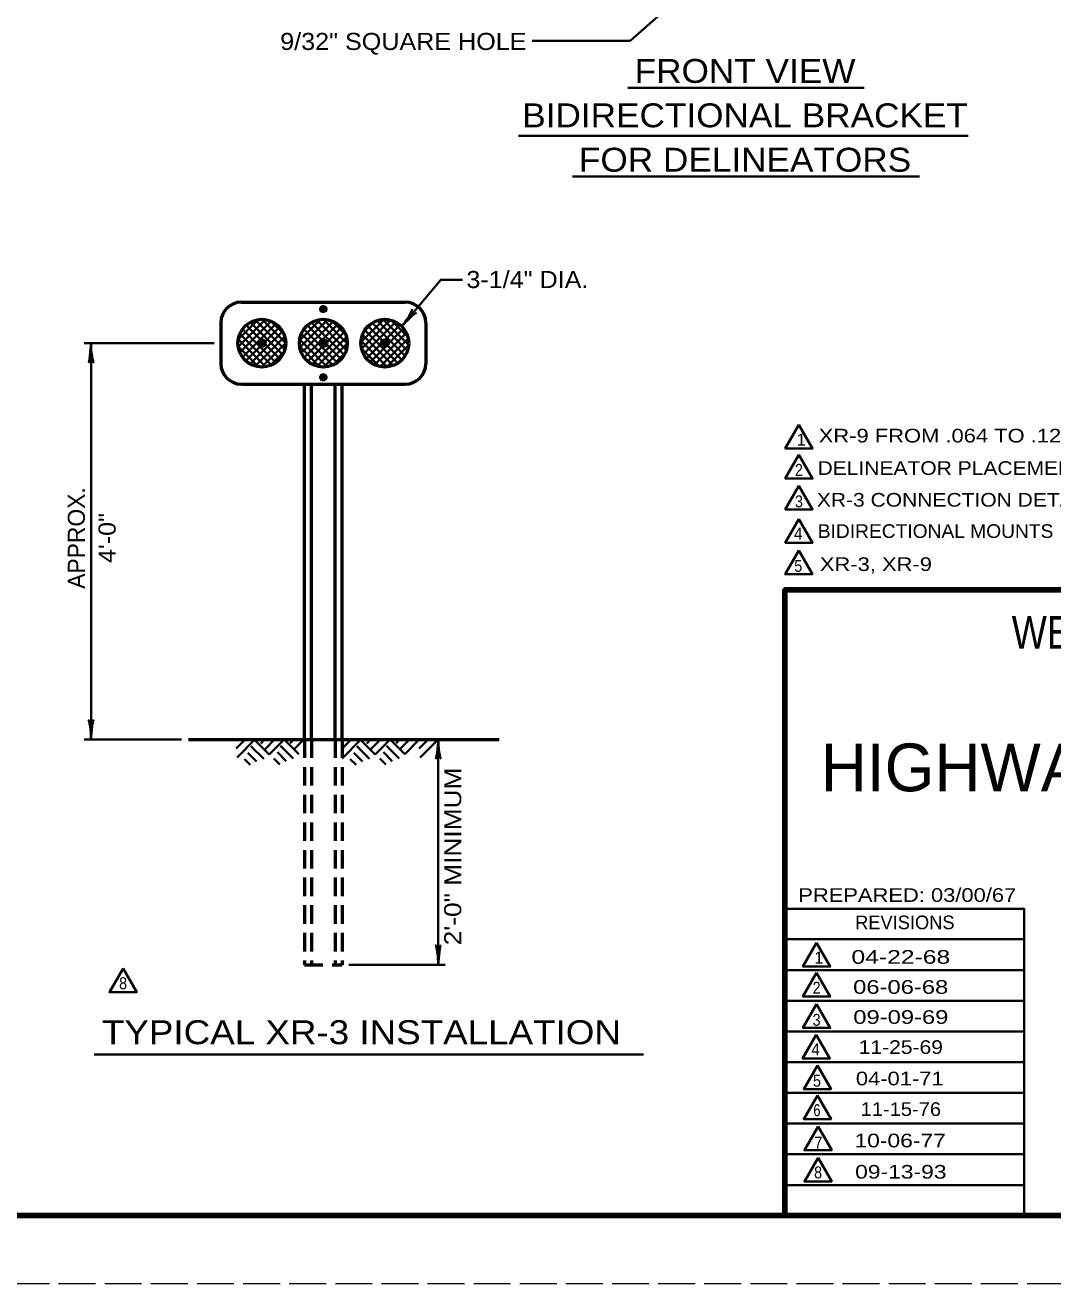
# Model space of a CAD drawing. Extents: x -54 to 626, y -41 to 399.
# Drawn here: x 331.9 to 482.3, y -41.3 to 142.9 of the extents above; entities that cross this region are included whole.
import ezdxf
from ezdxf.enums import TextEntityAlignment as Align

# ---------------------------------------------------------------- set-up
doc = ezdxf.new("R2010")
doc.units = 0
doc.header["$LTSCALE"] = 0.9
doc.linetypes.add('LONG_DASHED', pattern=[7.5, 6, -1.5])
doc.linetypes.add('MEDIUM_DASHED', pattern=[4.5, 3, -1.5])
doc.layers.add('1', color=7, linetype='Continuous', lineweight=35)
doc.layers.add('61', color=7, linetype='Continuous', lineweight=35)

msp = doc.modelspace()

# ---------------------------------------------------------------- hatches: boundary and pattern name
at = {"layer": '1'}
for points in [[(375.8723, 101.3772, 1), (375.1223, 101.3772, 1)], [(366.9973, 96.3772, 1), (365.9973, 96.3772, 1)], [(375.9973, 96.3772, 1), (374.9973, 96.3772, 1)], [(384.9973, 96.3772, 1), (383.9973, 96.3772, 1)], [(375.8723, 91.3772, 1), (375.1223, 91.3772, 1)]]:
    msp.add_hatch(color=256, dxfattribs=at).paths.add_polyline_path(points)

# ---------------------------------------------------------------- linework, layer by layer
at = {"layer": '1', "lineweight": 40}
for p, q in [((420.0461, 133.771), (454.6423, 133.771)), ((404.0612, 126.7473), (469.8797, 126.7473)), ((411.9789, 120.7698), (462.75, 120.7698)), ((341.9621, -7.7556), (422.3773, -7.7556))]:
    msp.add_line(p, q, dxfattribs=at)
at = {"layer": '1', "lineweight": 53}
for p, q in [((363.4973, 102.3772), (387.4973, 102.3772)), ((360.4973, 99.3772), (360.4973, 93.3772)), ((390.4973, 99.3772), (390.4973, 93.3772)), ((363.4973, 90.3772), (387.4973, 90.3772)), ((372.7473, 38.3772), (372.7473, 90.3772)), ((373.7473, 38.3772), (373.7473, 90.3772)), ((377.2473, 38.3772), (377.2473, 90.3772)), ((378.2473, 38.3772), (378.2473, 90.3772)), ((355.7473, 38.3772), (401.2473, 38.3772)), ((362.7473, 38.3772), (372.7473, 38.3772)), ((378.2473, 38.3772), (391.2473, 38.3772))]:
    msp.add_line(p, q, dxfattribs=at)
at = {"layer": '1'}
for p, q in [((363.0416, 96.9052), (365.9697, 99.8332)), ((363.042, 95.8449), (367.0292, 99.8322)), ((363.2739, 95.0162), (367.8578, 99.6002)), ((369.8656, 95.4361), (365.5557, 99.7459)), ((369.9965, 96.3657), (366.4857, 99.8766)), ((369.7433, 97.6797), (367.7995, 99.6234)), ((372.0235, 96.7808), (375.0932, 99.8506)), ((372.0598, 95.7564), (376.1179, 99.8146)), ((372.3092, 94.9452), (376.9291, 99.5651)), ((378.8588, 95.4161), (374.5358, 99.7392)), ((378.9949, 96.3407), (375.4607, 99.8749)), ((378.7571, 97.6392), (376.7591, 99.6372)), ((381.0072, 96.5281), (384.3465, 99.8673)), ((381.0992, 95.5594), (385.3152, 99.7755)), ((387.8011, 95.2447), (383.3649, 99.681)), ((387.9811, 96.1255), (384.2458, 99.8607)), ((387.8748, 97.2923), (385.4127, 99.7545)), ((367.8897, 93.1693), (363.2898, 97.7692)), ((363.6583, 94.3399), (368.5347, 99.2163)), ((368.5625, 93.5572), (363.6768, 98.4428)), ((364.1602, 93.7812), (369.0931, 98.7141)), ((369.1151, 94.0652), (364.1853, 98.9949)), ((364.7727, 93.3331), (369.541, 98.1013)), ((369.5568, 94.6841), (364.8046, 99.4364)), ((376.8717, 93.1605), (372.281, 97.7512)), ((377.5465, 93.5464), (372.6662, 98.4267)), ((372.7009, 94.2763), (377.5983, 99.1737)), ((372.9383, 98.7563), (373.1158, 98.9339)), ((378.1026, 94.051), (373.1712, 98.9824)), ((373.217, 93.7317), (378.1427, 98.6575)), ((378.5481, 94.6662), (373.7867, 99.4275)), ((373.8441, 93.2981), (378.5762, 98.0302)), ((381.3874, 94.787), (386.0875, 99.4871)), ((381.3887, 97.9702), (382.9039, 99.4855)), ((386.4095, 93.4544), (381.5746, 98.2893)), ((381.8078, 94.1467), (386.7276, 99.0664)), ((386.9958, 93.9287), (382.0492, 98.8753)), ((382.3432, 93.6214), (387.2532, 98.5315)), ((387.4599, 94.5252), (382.6451, 99.3401)), ((383.0027, 93.2202), (387.6542, 97.8718)), ((359.4973, 96.3772), (340.4973, 96.3772)), ((341.4973, 96.3772), (341.4973, 38.3772)), ((366.0276, 92.9101), (363.0292, 95.9084)), ((367.0687, 92.9297), (363.0501, 96.9483)), ((365.521, 93.0207), (369.854, 97.3537)), ((366.4421, 92.8811), (369.9936, 96.4326)), ((374.9943, 92.9167), (372.036, 95.875)), ((376.0464, 92.9252), (372.0457, 96.9259)), ((374.6008, 92.9942), (378.8799, 97.2733)), ((375.5473, 92.8801), (378.994, 96.3267)), ((384.8426, 92.9), (381.0197, 96.7228)), ((385.7043, 93.0989), (381.2188, 97.5845)), ((383.7983, 92.9552), (387.9192, 97.0761)), ((384.801, 92.8972), (387.9778, 96.074)), ((367.7289, 93.1072), (369.768, 95.1463)), ((376.9047, 93.1767), (378.6961, 94.9682)), ((383.7092, 92.9728), (381.0933, 95.5886)), ((386.4378, 93.4734), (387.401, 94.4366)), ((354.7473, 38.3772), (340.4973, 38.3772)), ((364.0673, 38.3372), (362.7473, 37.0172)), ((365.4872, 38.3372), (362.8673, 35.7172)), ((364.9072, 37.3772), (366.7672, 35.5372)), ((365.3872, 38.3372), (367.5872, 36.1372)), ((366.9072, 38.3372), (366.3472, 37.7572)), ((368.3472, 38.3372), (366.9672, 36.9572)), ((369.7672, 38.3372), (367.5872, 36.1372)), ((369.2473, 37.4372), (371.0872, 35.5972)), ((369.7672, 38.3372), (371.9072, 36.1972)), ((371.1873, 38.3372), (370.6672, 37.8172)), ((372.6273, 38.3372), (371.3073, 37.0172)), ((379.5673, 38.3372), (378.2473, 37.0172)), ((380.9872, 38.3372), (378.2473, 35.5972)), ((380.4072, 37.3772), (382.2672, 35.5372)), ((380.8872, 38.3372), (383.0872, 36.1372)), ((382.4072, 38.3372), (381.8472, 37.7572)), ((383.8472, 38.3372), (382.4672, 36.9572)), ((385.2672, 38.3372), (383.0872, 36.1372)), ((384.7473, 37.4372), (386.5872, 35.5972)), ((385.2672, 38.3372), (387.4072, 36.1972)), ((386.6873, 38.3372), (386.1672, 37.8172)), ((388.1273, 38.3372), (386.8073, 37.0172)), ((389.5472, 38.3372), (387.4072, 36.1972)), ((390.8673, 38.3372), (389.5472, 37.0172)), ((392.3272, 38.3772), (389.6672, 35.7172)), ((392.3237, 38.3772), (392.3237, 5.3772)), ((363.9472, 35.4972), (364.8073, 34.6572)), ((364.4472, 36.4172), (365.7272, 35.1372)), ((368.2672, 35.5572), (369.1273, 34.6972)), ((368.7872, 36.4772), (370.0673, 35.1972)), ((379.4472, 35.4972), (380.3073, 34.6572)), ((379.9472, 36.4172), (381.2272, 35.1372)), ((383.7672, 35.5572), (384.6273, 34.6972)), ((384.2872, 36.4772), (385.5673, 35.1972)), ((478.0577, 9.1039), (443.0777, 9.1039)), ((379.2473, 5.3772), (393.3237, 5.3772)), ((478.0577, 4.6039), (443.0777, 4.6039)), ((478.0577, 0.1039), (443.0777, 0.1039)), ((478.0577, -4.4161), (443.0777, -4.4161)), ((478.0577, -8.8961), (443.0777, -8.8961)), ((478.0577, -13.3761), (443.0777, -13.3761)), ((478.0577, -17.8761), (443.0777, -17.8761)), ((478.0577, -22.3761), (443.0777, -22.3761)), ((478.0577, -26.8961), (443.0777, -26.8961))]:
    msp.add_line(p, q, dxfattribs=at)
at = {"layer": '1', "linetype": 'MEDIUM_DASHED', "lineweight": 53}
for p, q in [((372.7473, 38.3772), (372.7473, 5.3772)), ((373.7473, 38.3772), (373.7473, 5.3772)), ((377.2473, 38.3772), (377.2473, 5.3772)), ((378.2473, 38.3772), (378.2473, 5.3772)), ((372.7473, 5.3772), (378.2473, 5.3772))]:
    msp.add_line(p, q, dxfattribs=at)
at = {"layer": '1'}
for points in [[(432.2431, 151.1188), (420.4005, 140.6441), (406.0473, 140.6441)], [(386.9721, 98.852), (392.6807, 105.6705), (395.8748, 105.6705)], [(478.0577, -31.3761), (478.0577, 13.5839), (443.0777, 13.5839)]]:
    msp.add_lwpolyline(points, dxfattribs=at)
for points in [[(445.1058, 84.4172), (443.1058, 80.9531), (447.1058, 80.9531)], [(445.1058, 80.0091), (443.1058, 76.545), (447.1058, 76.545)], [(445.1137, 75.5101), (443.1137, 72.046), (447.1137, 72.046)], [(445.1137, 70.6202), (443.1137, 67.1561), (447.1137, 67.1561)], [(445.0852, 66.0081), (443.0852, 62.544), (447.0852, 62.544)], [(447.6912, 8.5772), (445.6912, 5.1131), (449.6912, 5.1131)], [(346.1998, 4.8243), (344.1998, 1.3602), (348.1998, 1.3602)], [(447.6912, 4.1806), (445.6912, 0.7165), (449.6912, 0.7165)], [(447.6993, -0.3995), (445.6993, -3.8636), (449.6993, -3.8636)], [(447.6532, -4.8845), (445.6532, -8.3486), (449.6532, -8.3486)], [(447.8239, -9.367), (445.8239, -12.8311), (449.8239, -12.8311)], [(447.824, -13.7637), (445.824, -17.2278), (449.824, -17.2278)], [(447.905, -18.3087), (445.905, -21.7727), (449.905, -21.7727)], [(447.927, -22.8768), (445.927, -26.3409), (449.927, -26.3409)]]:
    msp.add_lwpolyline(points, close=True, dxfattribs=at)
at = {"layer": '1', "lineweight": 158}
msp.add_lwpolyline([(443.0577, -31.3361), (443.0577, 60.2439), (614.7178, 60.2439)], dxfattribs=at)
at = {"layer": '1', "lineweight": 53}
for centre, radius in [((375.4973, 101.3772), 0.375), ((366.4973, 96.3772), 3.5), ((375.4973, 96.3772), 3.5), ((384.4973, 96.3772), 3.5), ((366.4973, 96.3772), 0.5), ((375.4973, 96.3772), 0.5), ((384.4973, 96.3772), 0.5), ((375.4973, 91.3772), 0.375)]:
    msp.add_circle(centre, radius, dxfattribs=at)
for centre, start, end in [((363.4973, 99.3772), 90, 180), ((387.4973, 99.3772), 0, 90), ((363.4973, 93.3772), 180, 270), ((387.4973, 93.3772), 270, 0)]:
    msp.add_arc(centre, 3, start, end, dxfattribs=at)
at = {"layer": '1', "lineweight": 40}
for centre, major_axis, ratio, start_param, end_param in [((387.4607, 99.866), (-1.0266, -1.4694), 0.122415, 0.89635335, 3.14159265), ((387.8536, 99.5753), (1.2622, 1.234), 0.07063, 6.28230741, 8.55970261), ((341.2856, 95.2567), (0.1757, 1.7565), 0.07063, 3.14071475, 5.41810995), ((341.2856, 95.2567), (0.1757, 1.7565), 0.07063, 3.14071475, 5.41810995), ((341.7735, 95.286), (-0.1562, 1.7857), 0.122415, 0.89635335, 3.14159265), ((341.7735, 95.286), (-0.1562, 1.7857), 0.122415, 0.89635335, 3.14159265), ((341.221, 39.4684), (0.1562, -1.7857), 0.122415, 0.89635335, 3.14159265), ((341.7089, 39.4977), (-0.1757, -1.7565), 0.07063, 3.14071475, 5.41810995), ((392.1121, 37.2567), (0.1757, 1.7565), 0.07063, 3.14071475, 5.41810995), ((392.1121, 37.2567), (0.1757, 1.7565), 0.07063, 3.14071475, 5.41810995), ((392.6, 37.286), (-0.1562, 1.7857), 0.122415, 0.89635335, 3.14159265), ((392.6, 37.286), (-0.1562, 1.7857), 0.122415, 0.89635335, 3.14159265), ((392.0475, 6.4684), (0.1562, -1.7857), 0.122415, 0.89635335, 3.14159265), ((392.5354, 6.4977), (-0.1757, -1.7565), 0.07063, 3.14071475, 5.41810995)]:
    msp.add_ellipse(centre, major_axis=major_axis, ratio=ratio, start_param=start_param, end_param=end_param, dxfattribs=at)
at = {"layer": '61', "lineweight": 158}
msp.add_line((614.7178, -31.3361), (-24.3422, -31.3161), dxfattribs=at)
at = {"layer": '61', "linetype": 'LONG_DASHED', "lineweight": 13}
msp.add_line((625.6577, -41.3161), (-54.4022, -41.3361), dxfattribs=at)

# ---------------------------------------------------------------- texts
at = {"layer": '1'}
for s, height, width, p in [('9/32" SQUARE HOLE', 2.5, 1.1, (369.1856, 139.3047)), ('3-1/4" DIA.', 2.5, 1.1, (396.4385, 104.4488)), ('XR-9 FROM .064 TO .125, SPACING FORMULA ADDED, MEDIAN DETAIL.', 2, 1.2, (448.0093, 81.8416)), ('2', 1.75, 0.9, (444.525, 76.9551)), ('DELINEATOR PLACEMENT ON RAMP', 2, 1.15, (447.8386, 77.0917)), ('3', 1.75, 0.9, (444.525, 72.3419)), ('XR-3 CONNECTION DETAIL.', 2, 1.15, (447.7361, 72.4444)), ('4', 1.75, 0.95, (444.3883, 67.6262)), ('BIDIRECTIONAL MOUNTS', 2, 1.05, (447.8727, 67.8655)), ('5', 1.75, 0.9, (444.4251, 62.897)), ('XR-3, XR-9', 2, 1.2, (448.1757, 63.0242)), ('PREPARED: 03/00/67', 1.998, 1.2, (445.0177, 14.5839)), ('8', 1.75, 0.9, (345.6033, 1.7971)), ('2', 1.75, 0.9, (447.1104, 1.1266)), ('3', 1.75, 0.9, (447.1105, -3.5677)), ('TYPICAL XR-3 INSTALLATION', 3.5, 1.15, (343.0894, -6.252)), ('4', 1.75, 0.95, (446.9278, -7.8784)), ('5', 1.75, 0.9, (447.1638, -12.4781)), ('6', 1.75, 0.8, (447.2275, -16.7908)), ('7', 1.75, 0.9, (447.3721, -21.5425)), ('8', 1.75, 0.9, (447.3305, -25.904))]:
    msp.add_text(s, height=height, dxfattribs=dict(at, width=width)).set_placement(p)
for s, height, width, p in [('FRONT VIEW', 3.5, 1.1, (437.2261, 134.4862)), ('BIDIRECTIONAL BRACKET', 3.5, 1.1, (437.2261, 127.9862)), ('FOR DELINEATORS', 3.5, 1.1, (437.2261, 121.4862)), ('WEST VIRGINIA DIVISION OF HIGHWAYS', 4.795, 0.85, (529.7061, 51.6439)), ('04-22-68', 2, 1.35, (460.027, 5.5239)), ('06-06-68', 2, 1.3, (460.007, 1.1239)), ('09-09-69', 2, 1.3, (460.027, -3.2761)), ('11-25-69', 2, 1.15, (460.0271, -7.6761)), ('04-01-71', 2, 1.2, (459.867, -12.2761)), ('11-15-76', 2, 1.1, (460.027, -16.7561)), ('10-06-77', 2, 1.25, (459.9271, -21.3561)), ('09-13-93', 2, 1.25, (460.0271, -25.9361))]:
    msp.add_text(s, height=height, dxfattribs=dict(at, width=width)).set_placement(p, align=Align.CENTER)
for s, height, p in [('1', 1.75, (444.7983, 81.3973)), ('REVISIONS', 1.998, (453.3377, 10.5839)), ('1', 1.75, (447.3837, 5.5573))]:
    msp.add_text(s, height=height, dxfattribs=at).set_placement(p)
msp.add_text('APPROX.', height=2.5, rotation=90, dxfattribs=at).set_placement((340.5956, 67.8524), align=Align.CENTER)
at = {"layer": '1', "width": 1.1}
msp.add_text('4\'-0"', height=2.5, rotation=90, dxfattribs=at).set_placement((345.0956, 67.8525), align=Align.CENTER)
at = {"layer": '1'}
msp.add_text('HIGHWAY DELINEATORS-GENERAL', height=6.993, dxfattribs=at).set_placement((528.8481, 30.7742), align=Align.CENTER)
at = {"layer": '1', "width": 1.15}
msp.add_text('2\'-0" MINIMUM', height=2.5, rotation=90, dxfattribs=at).set_placement((395.6869, 8.2199))

doc.saveas('drawing.dxf')
